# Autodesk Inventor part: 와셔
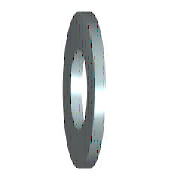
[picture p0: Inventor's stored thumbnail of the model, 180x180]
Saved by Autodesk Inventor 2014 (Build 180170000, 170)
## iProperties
IsCustomPart: 1
Created: 2012-02
Part Number: 와셔
Material: 강철, 연강
Description: 평면 와셔
Document SubType Name: Modeling
Standard: KS B 1326
Designer: mduedu
Standards Organization: KS
Language: ko-KR
Size Designation: 8x15.5
Categories: <MemberInstance><Categories><Category DisplayName="조임쇠" InternalName="e4da775c-781d-43d5-af7c-5136215cf5a6" Mnemonic="FSTN"><Category DisplayName="와셔" InternalN
Density: 1 g/cm^3
Appearance: 주황색
Author: mduedu
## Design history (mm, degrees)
sketch "스케치"
  geometry: C1 r 7.75 at (0, 0); C2 r 4.2 at (0, 0); 1 further point
  constraints: 2 centre point, 2 coincident
  dimensions: "d0" = 8.4 diameter of C2 (= SD1); "d1" = 15.5 diameter of C1 (= SD2)
extrude "본체" new body sketch "스케치" distance "d2" = 1.6 (= SD); taper "d3" = 0 deg
workaxis "Work Axis1"
workplane "Work Plane1"
body "Solid1"
other parameters: "SD1" = 8.4 [user parameter; used in 1 equation term], "SD2" = 15.5 [user parameter; used in 1 equation term], "SD" = 1.6 [user parameter; used in 1 equation term], "d4" = 0, "d5" = 0, "d6" = 0, "d7" = 0, "NND" = 8 [user parameter]
